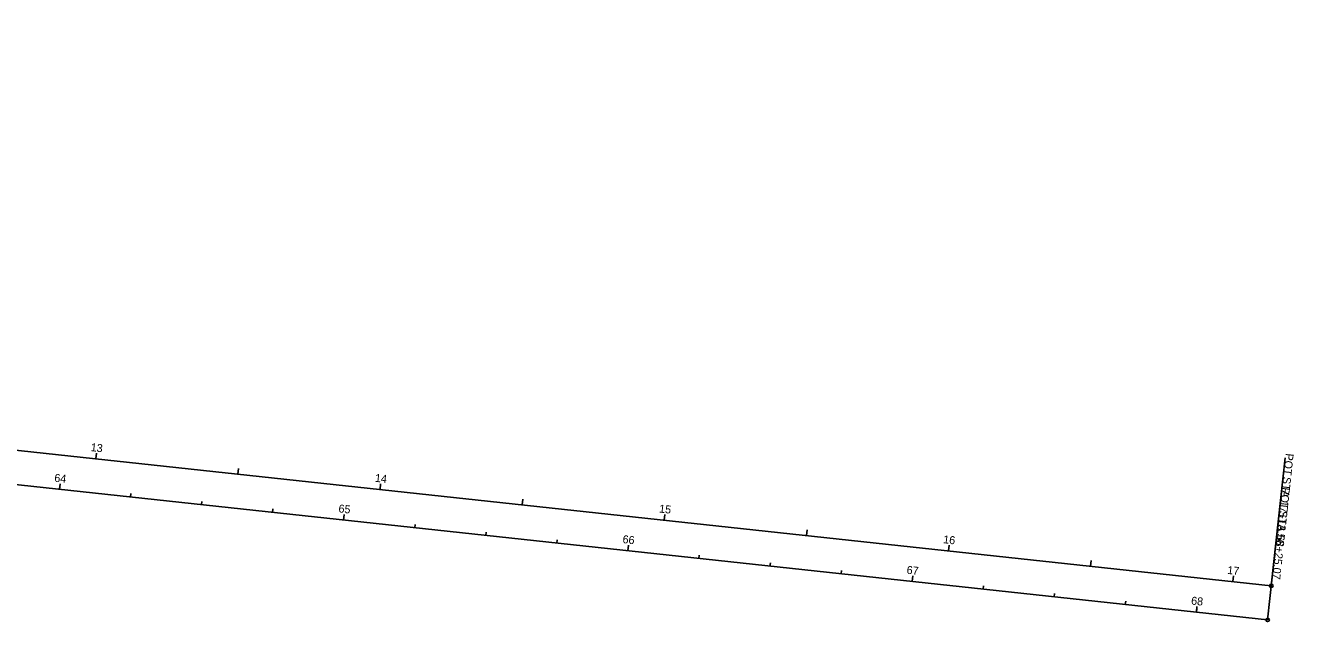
# Model space of a CAD drawing. Extents: x 1363416 to 1365241, y 422393 to 423801.
# Drawn here: x 1364797.5 to 1365241.1, y 423006.9 to 423215.5 of the extents above; entities that cross this region are included whole.
import ezdxf

# ---------------------------------------------------------------- set-up
doc = ezdxf.new("R2010")
doc.units = 0
for name, color, linetype in [('_CIVIL_CONSTRUCTION', 7, 'Continuous'), ('DT_X_Break_Line', 7, 'Continuous'), ('DT_X_Contour_Major', 7, 'Continuous'), ('DT_X_Triangles', 7, 'Continuous'), ('MD_P_CURB_FACE_TOP', 7, 'Continuous'), ('MD_P_SAWCUT', 7, 'Continuous')]:
    doc.layers.add(name, color=color, linetype=linetype)

msp = doc.modelspace()

# ---------------------------------------------------------------- linework, layer by layer
at = {"layer": '_CIVIL_CONSTRUCTION'}
msp.add_line((1363417.51, 423203.55), (1365232.02, 423007.54), dxfattribs=at)
at = {"layer": 'DT_X_Break_Line'}
for p, q in [((1363418.8, 423215.48), (1365233.31, 423019.47)), ((1364295.51, 423120.77), (1365233.31, 423019.47)), ((1365233.31, 423019.47), (1364295.51, 423120.77)), ((1364822.14, 423063.88), (1364822.36, 423065.87)), ((1365233.31, 423019.47), (1365238.14, 423064.21)), ((1364871.85, 423058.51), (1364872.07, 423060.5)), ((1364921.56, 423053.14), (1364921.78, 423055.13)), ((1364971.27, 423047.77), (1364971.49, 423049.76)), ((1365020.99, 423042.4), (1365021.2, 423044.39)), ((1365070.7, 423037.03), (1365070.91, 423039.02)), ((1365120.41, 423031.66), (1365120.62, 423033.65)), ((1365170.12, 423026.29), (1365170.33, 423028.28)), ((1365219.83, 423020.92), (1365220.04, 423022.91))]:
    msp.add_line(p, q, dxfattribs=at)
msp.add_circle((1365233.31, 423019.47), 0.6, dxfattribs=at)
at = {"layer": 'DT_X_Contour_Major'}
for p, q in [((1364809.41, 423053.19), (1364809.63, 423055.18)), ((1364834.27, 423050.5), (1364834.4, 423051.7)), ((1364859.12, 423047.82), (1364859.25, 423049.01)), ((1364883.98, 423045.13), (1364884.11, 423046.33)), ((1364908.83, 423042.45), (1364909.05, 423044.44)), ((1364933.69, 423039.76), (1364933.82, 423040.96)), ((1364958.54, 423037.08), (1364958.67, 423038.27)), ((1364983.4, 423034.39), (1364983.53, 423035.59)), ((1365008.25, 423031.71), (1365008.47, 423033.7)), ((1365033.11, 423029.02), (1365033.24, 423030.22)), ((1365057.96, 423026.34), (1365058.09, 423027.53)), ((1365082.82, 423023.65), (1365082.95, 423024.85)), ((1365107.68, 423020.97), (1365107.89, 423022.96)), ((1365132.53, 423018.28), (1365132.66, 423019.48)), ((1365157.39, 423015.6), (1365157.52, 423016.79)), ((1365182.24, 423012.91), (1365182.37, 423014.11)), ((1365207.1, 423010.23), (1365207.31, 423012.22)), ((1365231.95, 423007.54), (1365232.08, 423008.74))]:
    msp.add_line(p, q, dxfattribs=at)
at = {"layer": 'DT_X_Triangles'}
msp.add_line((1365232.02, 423007.54), (1365236.85, 423052.28), dxfattribs=at)
msp.add_circle((1365232.02, 423007.54), 0.6, dxfattribs=at)
at = {"layer": 'MD_P_CURB_FACE_TOP'}
msp.add_line((1365232.02, 423007.54), (1365236.85, 423052.28), dxfattribs=at)
msp.add_circle((1365232.02, 423007.54), 0.6, dxfattribs=at)
at = {"layer": 'MD_P_SAWCUT'}
for p, q in [((1364809.41, 423053.19), (1364809.54, 423054.38)), ((1364908.83, 423042.45), (1364909.05, 423044.44)), ((1365008.25, 423031.71), (1365008.38, 423032.9)), ((1365107.68, 423020.97), (1365107.8, 423022.16)), ((1365207.1, 423010.23), (1365207.23, 423011.42))]:
    msp.add_line(p, q, dxfattribs=at)

# ---------------------------------------------------------------- texts
at = {"layer": 'DT_X_Break_Line'}
for s, rotation, p in [('13', 353.8345, (1364820.27, 423066.6)), ('POT', 263.8345, (1365238.36, 423065.88)), ('14', 353.8345, (1364919.69, 423055.86)), (' STA. ', 263.8345, (1365237.59, 423058.73)), ('15', 353.8345, (1365019.08, 423045.12)), ('17+13.56', 263.8345, (1365236.57, 423049.33)), ('16', 353.8345, (1365118.45, 423034.39)), ('17', 353.8345, (1365217.81, 423023.65))]:
    msp.add_text(s, height=2.8, rotation=rotation, dxfattribs=at).set_placement(p)
at = {"layer": 'DT_X_Contour_Major'}
for s, p in [('64', (1364807.54, 423055.9)), ('65', (1364906.93, 423045.17)), ('66', (1365006.29, 423034.43)), ('67', (1365105.66, 423023.7)), ('68', (1365205.16, 423012.95))]:
    msp.add_text(s, height=2.8, rotation=353.8345, dxfattribs=at).set_placement(p)
at = {"layer": 'DT_X_Triangles'}
for s, p in [('POT', (1365237.08, 423054.01)), (' STA. ', (1365236.31, 423046.85)), ('68+25.07', (1365235.29, 423037.46))]:
    msp.add_text(s, height=2.8, rotation=263.8345, dxfattribs=at).set_placement(p)
at = {"layer": 'MD_P_CURB_FACE_TOP'}
for s, p in [('POT', (1365237.08, 423054.01)), (' STA. ', (1365236.31, 423046.85)), ('68+25.07', (1365235.29, 423037.46))]:
    msp.add_text(s, height=2.8, rotation=263.8345, dxfattribs=at).set_placement(p)
at = {"layer": 'MD_P_SAWCUT'}
msp.add_text('65', height=2.8, rotation=353.8345, dxfattribs=at).set_placement((1364906.93, 423045.17))

doc.saveas('drawing.dxf')
